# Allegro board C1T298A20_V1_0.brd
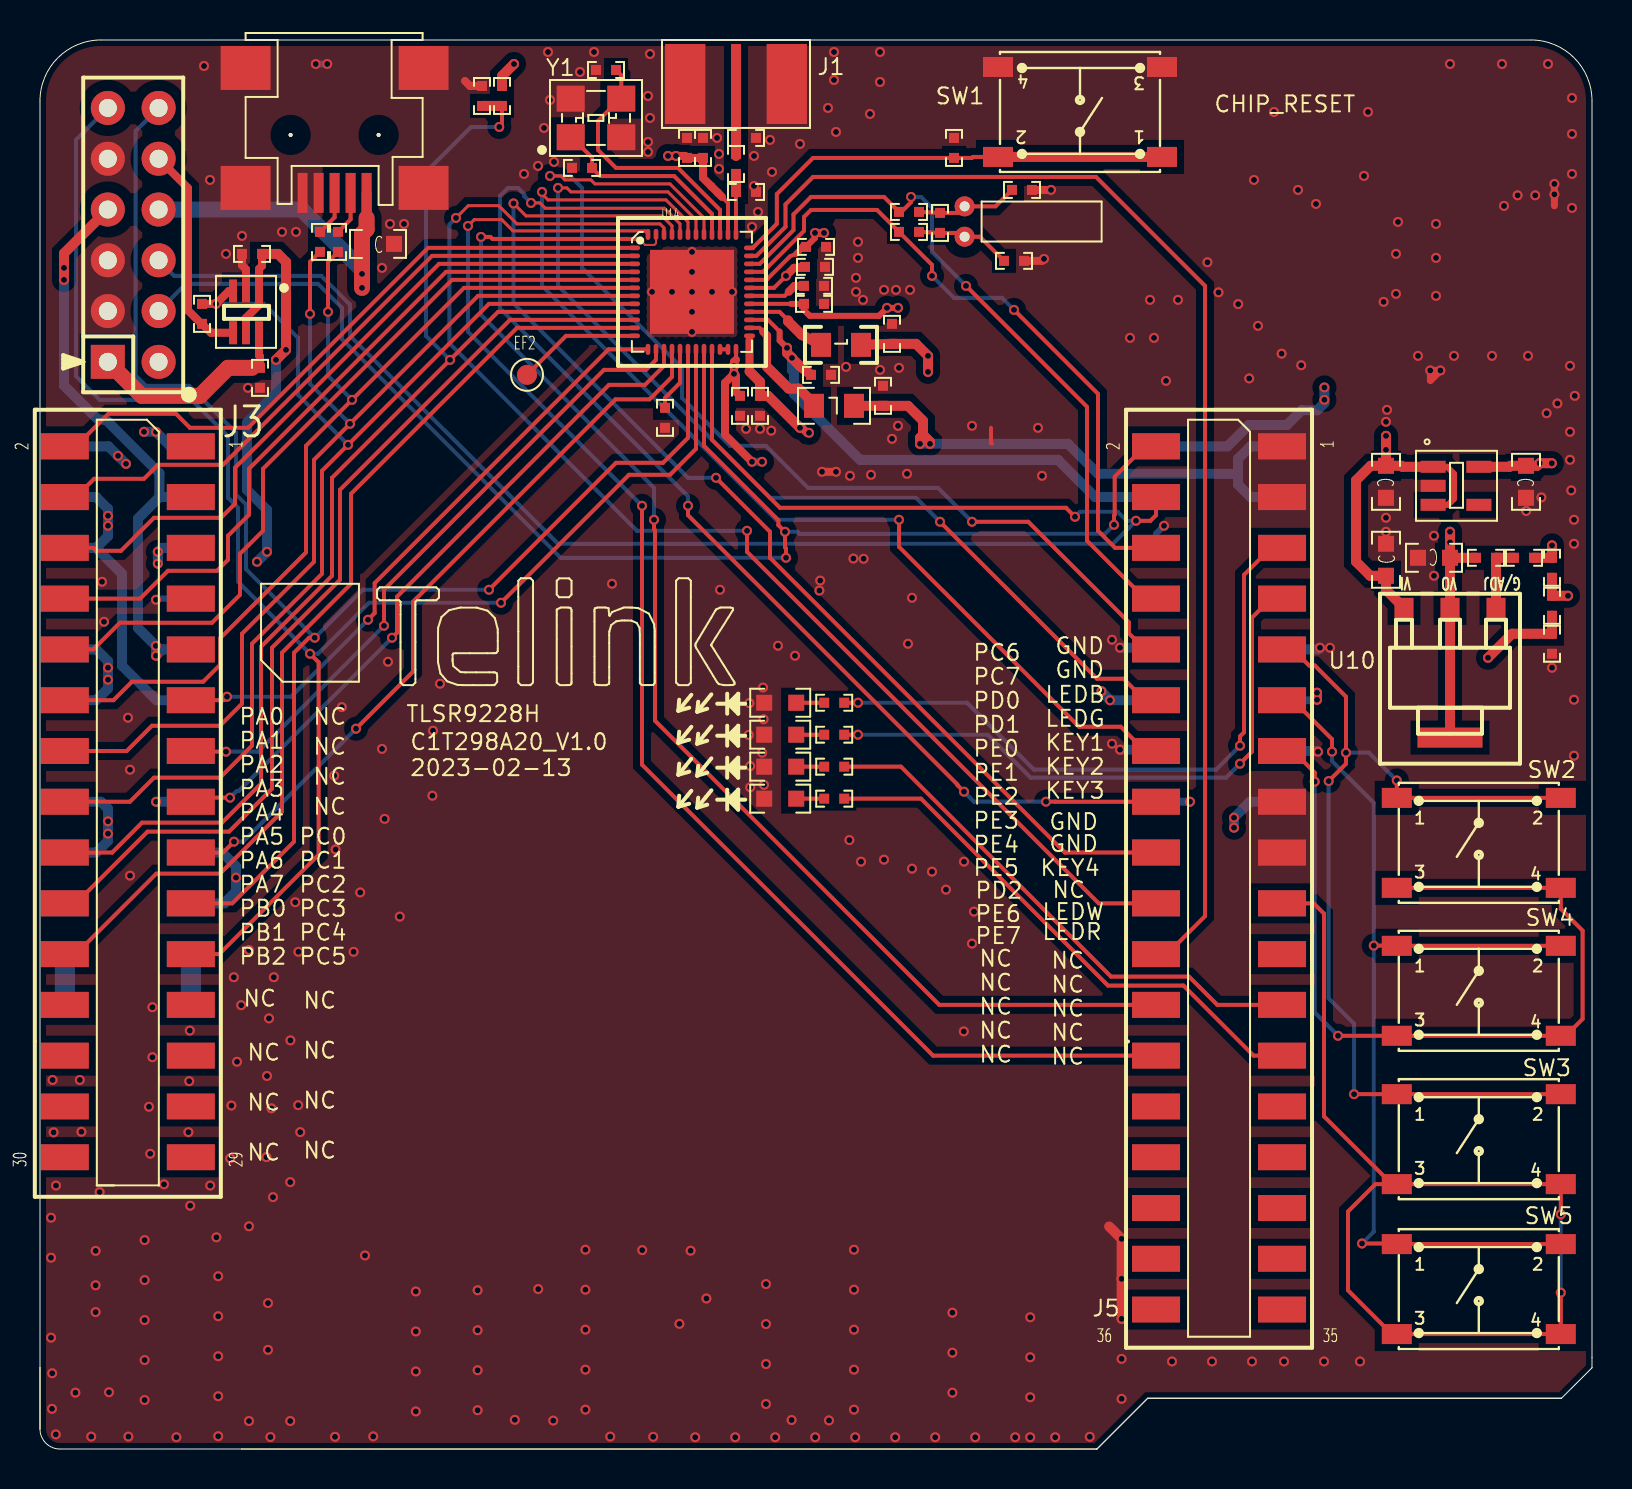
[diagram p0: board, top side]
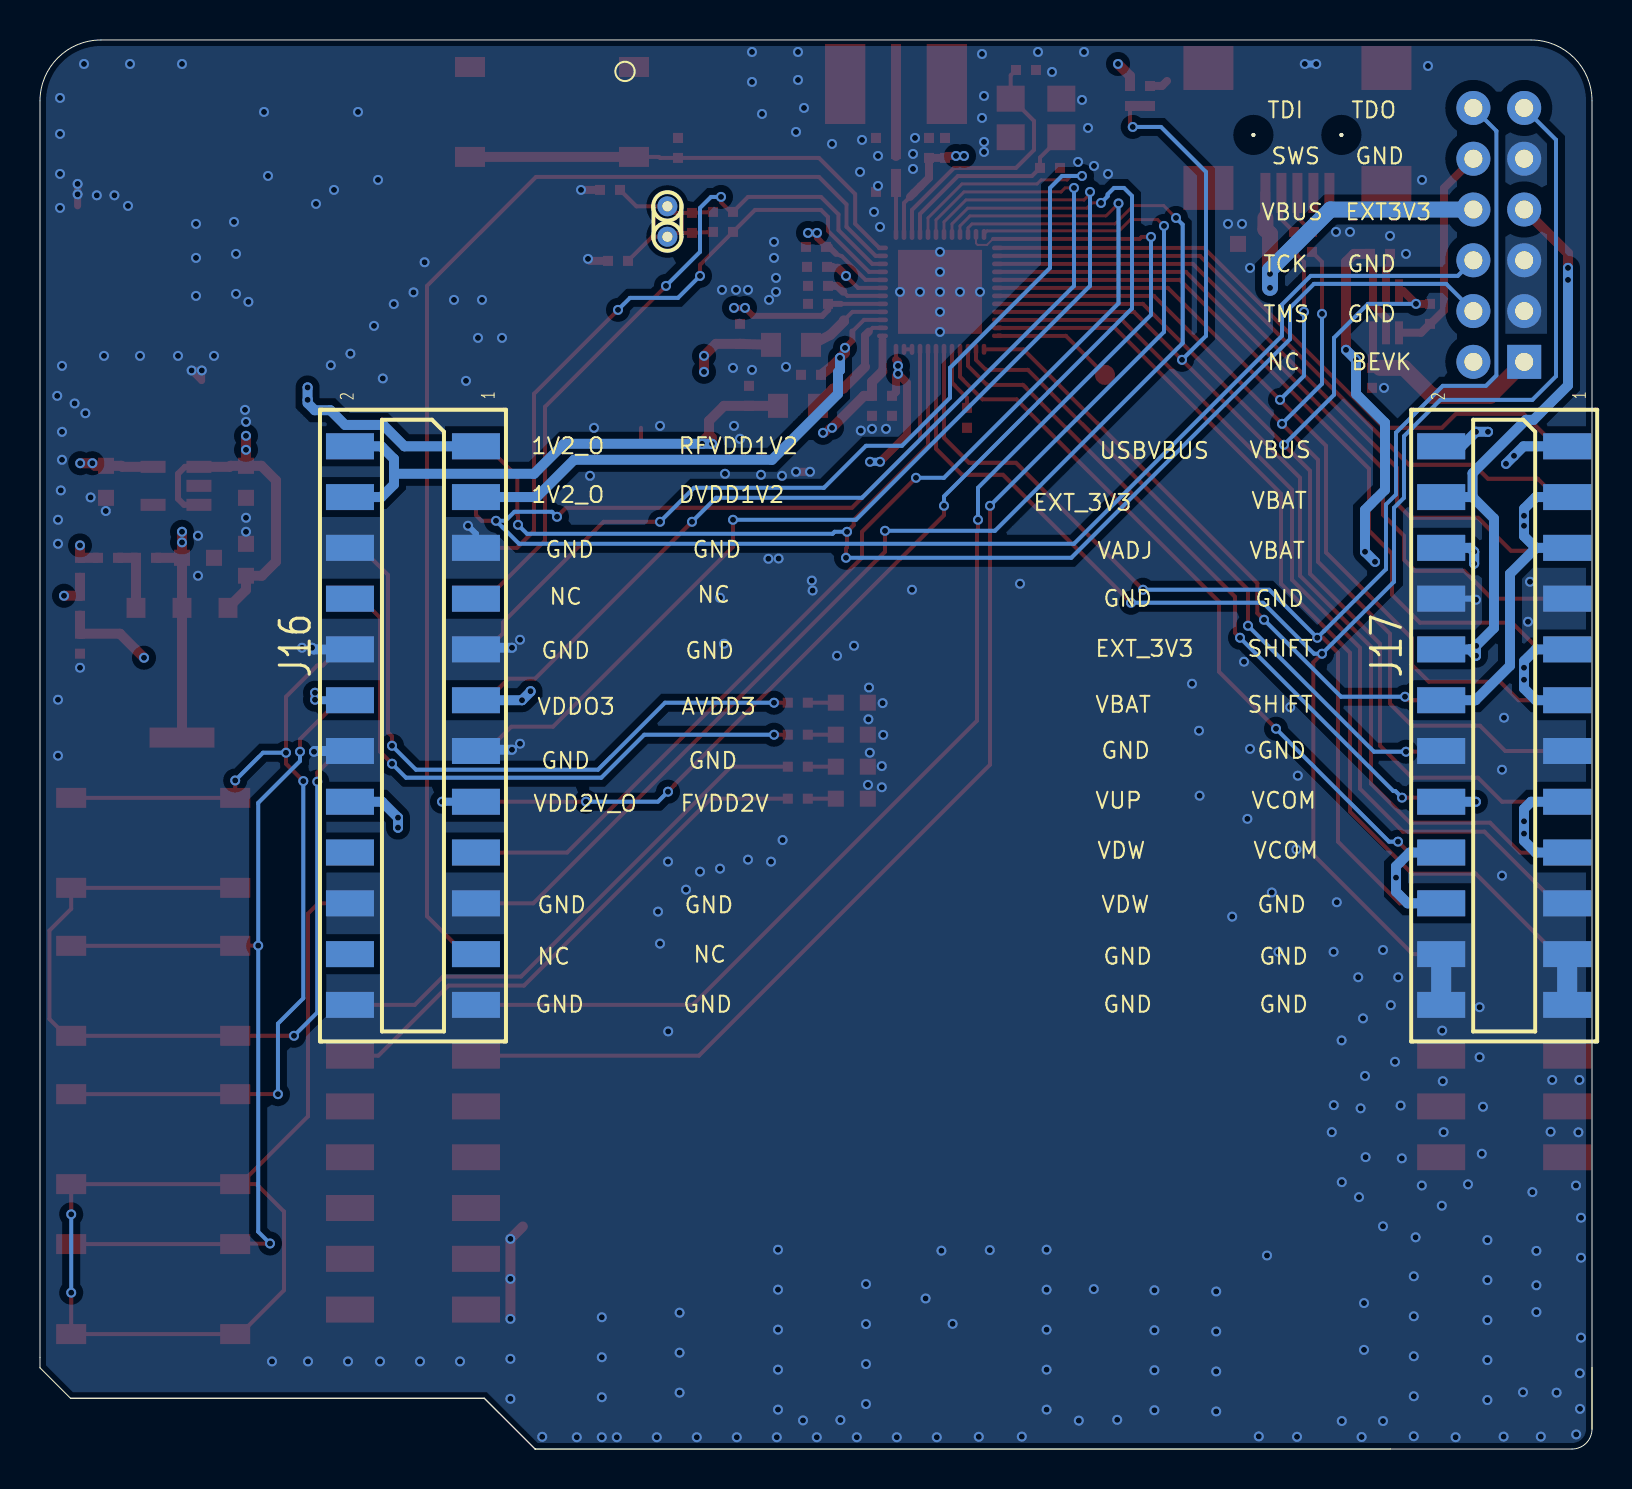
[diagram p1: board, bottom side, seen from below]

Outline 77.6 x 70.48 mm; copper layers: TOP, GND, POWER, BOTTOM. Coordinates in mm from the lower left corner of the outline.
Outline path: 0,4.08 0,67.43 arc(0.89,69.59) 3.05,70.48 74.55,70.48 arc(76.71,69.59) 77.6,67.43 77.6,4.06 76.08,2.54 76.07,2.54 ; 0,4.08 0,1 ; 0,4.08 0,1 ; 0,1 arc(0.29,0.29) 1,0 10.08,0 ; 10.08,0 52.84,0 ; 10.08,0 52.84,0 ; 52.84,0 52.85,0 ; 52.84,0 52.85,0 ; 52.85,0 55.39,2.54 ; 52.85,0 55.39,2.54 ; 55.39,2.54 76.07,2.54 ; 55.39,2.54 76.07,2.54

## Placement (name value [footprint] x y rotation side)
C1  NC  [0402]  28.3 68.98 0 top
C2  NC  [0402]  27.1 64.08 0 top
C3  0.1uF  [0402]  33.15 65.08 90 top
C4  2.2uF  [0402]  32.35 65.08 90 top
C5  NC  [0402]  35.3 62.88 180 top
C6  NC  [0402]  35.3 65.58 180 top
C7  NC  [0402]  48.7 59.43 180 top
C8  NC  [0402]  49.1 62.98 180 top
C9  1uF  [0402]  45.7 65.08 90 top
C10  1uF  [0402]  38.8 60.13 0 top
C11  1uF  [0402]  38.75 59.13 0 top
C12  1uF  [0402]  38.7 57.28 0 top
C13  1uF  [0402]  38.7 58.18 0 top
C14  1uF  [0402]  42.6 55.78 90 top
C17  1uF  [0402]  39.05 53.73 0 top
C18  1uF  [0402]  36 52.18 270 top
C21  1uF  [0402]  42.15 52.68 90 top
C23  1uF  [0402]  31.25 51.58 270 top
C30  10uF  [0603C]  16.9 60.28 0 top
C33  0.1uF  [0402]  10.6 59.78 180 top
C34  0.1uF  [0402]  11 53.58 270 top
C37  10uF  [0603C]  67.3 44.48 90 top
C38  10uF  [0603C]  67.3 48.38 270 top
C39  10uF  [0603C]  74.3 48.38 270 top
C40  10uF  [0603C]  69.7 44.58 180 top
C41  1uF  [0402]  35 52.18 270 top
D1  Blue  [0603-LED]  37.01 37.33 180 top
D2  Green  [0603-LED]  37.01 35.73 180 top
D3  White  [0603-LED]  37.01 34.13 180 top
D4  Red  [0603-LED]  37.01 32.53 180 top
EF2  TP  [TP100]  24.35 53.73 0 top
J1  RFIN  [SMA-H]  34.8 68.28 270 top
J3  HEADER 18X2  [SMD254M-2X15_RX1_30Y2_40]  4.39 23.49 90 top
J5  HEADER 18X2  [SMD254M-2X18_RX1_30Y2_40]  58.95 23.49 90 top
J11  USB_MiniABF  [USB-MINI-F5]  14.73 62.83 180 top
J15  JTAG  [HDR254F-2X6X850]  3.39 67.08 270 top
J16  HEADER 12X2  [SMD254M-2X12_RX1_30Y2_40]  58.95 36.19 90 bottom
J17  HEADER 12X2  [SMD254M-2X12_RX1_30Y2_40]  4.39 36.19 90 bottom
L1  0R  [0402]  34.8 64.28 90 top
L2  2.2uH  [0805L]  40.05 55.23 0 top
L3  2.2uH  [0805L]  39.7 52.18 0 top
R1  NC  [0402]  43.45 60.88 180 top
R2  NC  [0402]  43.45 61.88 180 top
R3  NC  [0402]  45 61.33 90 top
R4  1K  [0402]  39.71 37.33 180 top
R5  1K  [0402]  39.71 35.73 180 top
R6  1K  [0402]  39.71 34.13 180 top
R7  1K  [0402]  39.71 32.53 180 top
R14  33  [0402R]  14.9 60.38 270 top
R15  33  [0402R]  14 60.38 270 top
R16  NC/1K  [0402]  23.1 67.68 270 top
R17  1M/NC  [0402]  22.1 67.68 270 top
R26  0R  [0402R]  8.1 56.78 270 top
R33  430R  [0402]  74.2 44.58 0 top
R34  1.15K  [0402]  75.6 44.08 270 top
R35  787R  [0402]  75.6 42.18 270 top
R36  464R  [0402]  75.6 40.28 270 top
R37  1K  [0402]  72.3 44.58 180 top
SW1  SW4PIN_4.5x4.5  [SW_6X6_SMD]  52 66.88 180 top
SW2  SW4PIN_4.5x4.5  [SW_6X6_SMD]  71.94 30.32 0 top
SW3  SW4PIN_4.5x4.5  [SW_6X6_SMD]  71.94 15.5 0 top
SW4  SW4PIN_4.5x4.5  [SW_6X6_SMD]  71.94 22.92 0 top
SW5  SW4PIN_4.5x4.5  [SW_6X6_SMD]  71.94 8 0 top
U8  NC/TXS0101  [SC70-6]  10.3 56.88 180 top
U10  LM1117-ADJ  [SOT-223]  70.5 38.58 180 top
U11  CE1132-33M  [SOT-23-5]  70.8 48.18 270 top
U14  TLSR9228H  [QFN_6X6_48PIN_0P4_4P2X4P2]  32.6 57.88 0 top
Y1  24MHz-12pF-+/-20ppm  [OSCCC250X320X110]  27.8 66.58 90 top
Y2  32.768KHz - 9pf - +/-20ppm  [OSC_2X6]  50.23 61.4 180 top

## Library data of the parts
C1 C2 = C1005_NC
C3 C4 C9-C14 C17 C18 C21 C23 C38 C39 C41 = C1005X5R1C104K
C5-C8 = C1608_NC
C30 C37 = C1608X5R0J106M
C33 C34 C40 = C1608X5R1C105M
D1-D4 = 0603D_Green
EF2 = TestPad100
J1 = SMA_JACK_2
J3 = HEADER 18X2_0: Tolerance: RichardLC
J5 = HEADER 18X2: Tolerance: RichardLC
J11 = USB_MiniABF_5pin: User Part Number: pn; Tolerance: RichardLC
J15 = HEADER 6X2: User Part Number: pn; Tolerance: RichardLC
J16 J17 = HEADER 12X2: Tolerance: RichardLC
L1 = MLK1608_000R
L2 L3 = IND
R1-R3 R26 = RS0603K102JT
R4-R7 = RS0402K102JT
R14 R15 = RS0603K330JT
R16 R17 = RS0402K104JT
R33-R37 = RS0603K104JT
SW1-SW5 = SW_6X6_SMD_0
U8 = TXS0101
U10 = XC62FP3302_0.3V_SOT-89
U11 = XC6219_6.3V_SOT-23-5
U14 = TLSR9228H_0
Y1 = CRYSTAL4/SM_0: Tolerance: RichardLC
Y2 = OSC_2x6_2pin_16Mhz

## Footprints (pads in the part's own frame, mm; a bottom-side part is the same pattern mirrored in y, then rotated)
0402
  rect 0.5x0.5 smd: 1(-0.5,0) 2(0.5,0)
0402R
  rect 0.5x0.5 smd: 1(-0.5,0) 2(0.5,0)
0603-LED
  rect 0.8x0.8 smd: A(-0.8,0) C(0.8,0)
0603C
  rect 0.8x0.8 smd: 1(-0.8,0) 2(0.8,0)
0805L
  rect 1x1.2 smd: 1(-1,0) 2(1,0)
HDR254F-2X6X850
  rect 1.7x1.7 hole 0.9: 1(12.7,0)
  round 1.7 hole 0.9: 2(12.7,2.54) 3(10.16,0) 4(10.16,2.54) 5(7.62,0) 6(7.62,2.54) 7(5.08,0) 8(5.08,2.54) 9(2.54,0) 10(2.54,2.54) 11(0,0) 12(0,2.54)
OSC_2X6
  round 1 hole 0.5: 1(4,0.76) 2(4,-0.76)
OSCCC250X320X110
  rect 1.3x1.4 smd: 1(-0.965,1.265) 2(-0.965,-1.265) 3(0.965,-1.265) 4(0.965,1.265)
QFN_6X6_48PIN_0P4_4P2X4P2
  oval 0.55x0.23 smd: 1(-2.875,2.2) 2(-2.875,1.8) 3(-2.875,1.4) 4(-2.875,1) 5(-2.875,0.6) 6(-2.875,0.2) 7(-2.875,-0.2) 8(-2.875,-0.6) 9(-2.875,-1) 10(-2.875,-1.4) 11(-2.875,-1.8) 12(-2.875,-2.2) 25(2.875,-2.2) 26(2.875,-1.8) 27(2.875,-1.4) 28(2.875,-1) 29(2.875,-0.6) 30(2.875,-0.2) 31(2.875,0.2) 32(2.875,0.6) 33(2.875,1) 34(2.875,1.4) 35(2.875,1.8) 36(2.875,2.2)
  oval 0.23x0.55 smd: 13(-2.2,-2.875) 14(-1.8,-2.875) 15(-1.4,-2.875) 16(-1,-2.875) 17(-0.6,-2.875) 18(-0.2,-2.875) 19(0.2,-2.875) 20(0.6,-2.875) 21(1,-2.875) 22(1.4,-2.875) 23(1.8,-2.875) 24(2.2,-2.875) 37(2.2,2.875) 38(1.8,2.875) 39(1.4,2.875) 40(1,2.875) 41(0.6,2.875) 42(0.2,2.875) 43(-0.2,2.875) 44(-0.6,2.875) 45(-1,2.875) 46(-1.4,2.875) 47(-1.8,2.875) 48(-2.2,2.875)
  rect 4.2x4.2 smd: 49(0,0)
SC70-6
  rect 0.4x1.15 smd: 1(-0.65,-1.045) 2(0,-1.045) 3(0.65,-1.045) 4(0.65,1.045) 5(0,1.045) 6(-0.65,1.045)
SMA-H
  rect 4x0.5 smd: 1(0,0)
  rect 4x2 smd: 2(0,-2.54) 3(0,2.54) 4(0,-2.54) 5(0,2.54)
SMD254M-2X12_RX1_30Y2_40
  rect 1.3x2.4 smd: 1(13.97,-3.15) 2(13.97,3.15) 3(11.43,-3.15) 4(11.43,3.15) 5(8.89,-3.15) 6(8.89,3.15) 7(6.35,-3.15) 8(6.35,3.15) 9(3.81,-3.15) 10(3.81,3.15) 11(1.27,-3.15) 12(1.27,3.15) 13(-1.27,-3.15) 14(-1.27,3.15) 15(-3.81,-3.15) 16(-3.81,3.15) 17(-6.35,-3.15) 18(-6.35,3.15) 19(-8.89,-3.15) 20(-8.89,3.15) 21(-11.43,-3.15) 22(-11.43,3.15) 23(-13.97,-3.15) 24(-13.97,3.15)
SMD254M-2X15_RX1_30Y2_40
  rect 1.3x2.4 smd: 1(26.67,-3.15) 2(26.67,3.15) 3(24.13,-3.15) 4(24.13,3.15) 5(21.59,-3.15) 6(21.59,3.15) 7(19.05,-3.15) 8(19.05,3.15) 9(16.51,-3.15) 10(16.51,3.15) 11(13.97,-3.15) 12(13.97,3.15) 13(11.43,-3.15) 14(11.43,3.15) 15(8.89,-3.15) 16(8.89,3.15) 17(6.35,-3.15) 18(6.35,3.15) 19(3.81,-3.15) 20(3.81,3.15) 21(1.27,-3.15) 22(1.27,3.15) 23(-1.27,-3.15) 24(-1.27,3.15) 25(-3.81,-3.15) 26(-3.81,3.15) 27(-6.35,-3.15) 28(-6.35,3.15) 29(-8.89,-3.15) 30(-8.89,3.15)
SMD254M-2X18_RX1_30Y2_40
  rect 1.3x2.4 smd: 1(26.67,-3.15) 2(26.67,3.15) 3(24.13,-3.15) 4(24.13,3.15) 5(21.59,-3.15) 6(21.59,3.15) 7(19.05,-3.15) 8(19.05,3.15) 9(16.51,-3.15) 10(16.51,3.15) 11(13.97,-3.15) 12(13.97,3.15) 13(11.43,-3.15) 14(11.43,3.15) 15(8.89,-3.15) 16(8.89,3.15) 17(6.35,-3.15) 18(6.35,3.15) 19(3.81,-3.15) 20(3.81,3.15) 21(1.27,-3.15) 22(1.27,3.15) 23(-1.27,-3.15) 24(-1.27,3.15) 25(-3.81,-3.15) 26(-3.81,3.15) 27(-6.35,-3.15) 28(-6.35,3.15) 29(-8.89,-3.15) 30(-8.89,3.15) 31(-11.43,-3.15) 32(-11.43,3.15) 33(-13.97,-3.15) 34(-13.97,3.15) 35(-16.51,-3.15) 36(-16.51,3.15)
SOT-23-5
  rect 0.6x1.25 smd: 1(-0.95,-1.145) 2(0,-1.145) 3(0.95,-1.145) 4(0.95,1.145) 5(-0.95,1.145)
SOT-223
  rect 0.95x1 smd: 1(-2.3,-3.495) 2(0,-3.495) 3(2.3,-3.495)
  rect 3.25x1 smd: 4(0,2.995)
SW_6X6_SMD
  rect 1.5x1 smd: 1(-4.1,2.25) 2(4.1,2.25) 3(-4.1,-2.25) 4(4.1,-2.25)
TP100
  round 1 smd: 1(0,0)
USB-MINI-F5
  round 0.2 hole 0.9 unplated: (-2.2,-2.9) (2.2,-2.9)
  rect 0.5x2 smd: 1(-1.6,0) 2(-0.8,0) 3(0,0) 4(0.8,0) 5(1.6,0)
  rect 2.5x2.2 smd: 6(-4.45,-6.25) 7(4.45,-6.25) 8(-4.45,-0.25) 9(4.45,-0.25)

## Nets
GND: C1.1 C2.1 C3.2 C4.2 C5.1 C6.1 C7.1 C8.1 C9.2 C10.2 C11.2 C12.2 C13.2 C14.2 C17.2 C18.2 C21.2 C23.2 C30.2 C33.2 C34.2 C37.2 C38.2 C39.2 C40.2 C41.2 D1.C(CATHODE) D2.C(CATHODE) D3.C(CATHODE) D4.C(CATHODE) J1.2 J1.3 J1.4 J1.5 J5.1 J5.3 J5.15 J5.17 J11.4(ID) J11.5(GND) J11.6(S1) J11.7(S2) J11.8(S3) J11.9(S4) J15.3 J15.5 J15.9 J16.5 J16.6 J16.9 J16.10 J16.13 J16.14 J16.19 J16.20 J16.23 J16.24 J17.7 J17.8 J17.13 J17.14 J17.19 J17.21 J17.22 J17.23 J17.24 R17.1 R36.2 SW1.3 SW1.4 U8.2(GND) U11.2(VSS) U14.49(GND) Y1.2 Y1.4
VBAT_ADJ: C40.1 J17.6 R37.2 U10.2(VOUT#2) U10.4(VOUT#4)
VBUS: C30.1 C37.1 C38.1 J11.1(V_BUS) J15.8 J17.2 U10.3(VIN) U11.1(VIN) U11.3(CE)
BEVK_3V3: C34.1 J15.1 U8.6(VCCB)
BEVK_SWS: J15.10 R26.2 U8.4(B)
EXT_3V3: C39.1 J15.7 J17.4 J17.10 R16.1 U11.5(VOUT)
LED_B: J5.5 R4.1
LED_G: J5.7 R5.1
LED_R: J5.25 R7.1
LED_W: J5.23 R6.1
LEVEL_SHIFT: C33.1 J17.9 J17.11 U8.1(VCCA) U8.5(OE)
N: U14.22(N#22) U14.23(N#23)
TL_AVDD3: C10.1 J16.11 U14.32(AVDD3)
TL_DVDD1V2: C17.1 J16.3 U14.27(VDD1V4)
TL_FVDD2V: C12.1 J16.15 U14.29(FVDD2V)
TL_KEY1: J5.9 SW2.1 SW2.2 SW3.1 SW3.2
TL_KEY2: J5.11 SW4.1 SW4.2 SW5.1 SW5.2
TL_KEY3: J5.13 SW2.3 SW2.4 SW4.3 SW4.4
TL_KEY4: J5.19 SW3.3 SW3.4 SW5.3 SW5.4
TL_PA0: J3.2 U14.1(PA0)
TL_PA1: J3.4 U14.2(PA1)
TL_PA2: J3.6 U14.3(PA2)
TL_PA3: J3.8 U14.4(PA3)
TL_PA4: J3.10 U14.5(PA4)
TL_PA5_DM: J3.12 R14.2 U14.6(PA5)
TL_PA6_DP: J3.14 R15.2 U14.7(PA6)
TL_PA7_SWS: J3.16 R26.1 U8.3(A) U14.8(PA7)
TL_PB0: J3.18 R16.2 R17.2 U14.9(PB0)
TL_PB1: J3.20 U14.10(PB1)
TL_PB2: J3.22 U14.11(PB2)
TL_PC0: J3.11 U14.13(PC0)
TL_PC1: J3.13 U14.14(PC1)
TL_PC2: J3.15 U14.15(PC2)
TL_PC3: J3.17 U14.16(PC3)
TL_PC4_TDI: J3.19 J15.12 U14.18(PC4)
TL_PC5_TDO: J3.21 J15.11 U14.19(PC5)
TL_PC6_TMS: J5.2 J15.4 U14.20(PC6)
TL_PC7_TCK: J5.4 J15.6 U14.21(PC7)
TL_PD0_32K: J5.6 R1.2 U14.33(PD0)
TL_PD1_32K: J5.8 R2.2 U14.34(PD1)
TL_PD2: J5.22 U14.35(PD2)
TL_PE0: J5.10 U14.41(PE0)
TL_PE1: J5.12 U14.42(PE1)
TL_PE2: J5.14 U14.43(PE2)
TL_PE3: J5.16 U14.44(PE3)
TL_PE4: J5.18 U14.45(PE4)
TL_PE5: J5.20 U14.46(PE5)
TL_PE6: J5.24 U14.47(PE6)
TL_PE7: J5.26 U14.48(PE7)
TL_RFVDD1V2: C3.1 C4.1 J16.1 U14.38(VLINE_PAD)
TL_RST: C9.1 SW1.1 SW1.2 U14.36(RESETB)
TL_VBAT: C18.1 J17.3 J17.5 J17.12 U14.25(VBAT)
TL_VBUS: C11.1 J17.1 U14.31(VBUS)
TL_VDD1V2_O: C21.1 J16.2 J16.4 L3.2
TL_VDD2V_O: C14.1 J16.16 L2.2
TL_VDD3: C41.1 J16.12 U14.24(VDD3)
TL_XC1: C1.2 U14.39(XC1) Y1.3
TL_XC2: C2.2 U14.40(XC2) Y1.1
VCOM: J17.15 J17.17 R34.2 R35.1
VDW: J17.18 J17.20 R35.2 R36.1
VUP: J17.16 R33.2 R34.1
N20012529: C7.2 R1.1 R3.1 Y2.1
N20012531: C8.2 R2.1 R3.2 Y2.2
N20028206: R33.1 R37.1 U10.1(ADJ)
N20031284: C23.1 U14.17(VDDDEC)
N20031302: L3.1 U14.26(VDD1V4_O)
N20031350: L2.1 U14.28(VDD2V_O)
N20031395: C13.1 U14.30(VDDPST_F)
N20031510: C6.2 J1.1 L1.2
N20031514: C5.2 L1.1 U14.37(ANT)
N20050417: J11.3(D+) R15.1
N20050429: J11.2(D-) R14.1
N20105309: EF2.1(TP) U14.12(VDD25_EF)
N200358921: D4.A(ANODE) R7.2
N200359000: D1.A(ANODE) R4.2
N200359081: D2.A(ANODE) R5.2
N200359160: D3.A(ANODE) R6.2

Pads without a net: J3 1 3 5 7 9 23 24 25 26 27 28 29 30; J5 21 27 28 29 30 31 32 33 34 35 36; J15 2; J16 7 8 17 18 21 22; U11 4

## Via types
v1: diameter 0.5, hole 0.3, TOP to BOTTOM, 448 vias

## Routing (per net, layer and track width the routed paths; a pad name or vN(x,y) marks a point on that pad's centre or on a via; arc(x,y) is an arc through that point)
GND: length 30.7
  TOP w0.2: J5.3 61.55,47.62 ; 47.55,51.08 47.55,50.33 47.6,50.28
  TOP w0.35: v1(75.72,63.28) v1(75.72,62.76) 75.72,62.19 ; 69.52,53.45 69.52,53.94 v1(69.51,53.95) v1(70.02,53.95) 69.52,53.45
  TOP w0.4: v1(39.1,48.88) v1(39.8,48.88) ; v1(50.2,59.53) 50.1,59.43 C7.1 ; C33.2 10.1,59.21 10.3,59.01 U8.2 ; R17.1 21.5,68.18 21.25,68.43 ; C8.1 v1(50.55,62.98)
  TOP w0.5: 53.46,11.13 v1(54.08,10.51) v1(54.08,8.51) v1(54.08,6.51)
  BOTTOM w0.3: J17.8 5.86,42.54 v1(5.8,42.48) ; J16.5 55.8,45.78 v1(56.2,46.18)
  BOTTOM w0.35: v1(14.36,69.28) 14.3,69.28 13.8,69.28 13.8,69.28 v1(13.79,69.28)
  BOTTOM w0.5: v1(64,40.08) 63.92,40 J16.10 ; J16.14 63.86,34.92 v1(63.9,34.88) ; 56.2,40.08 v1(54,40.08) ; 55.4,34.98 v1(54,34.98)
  BOTTOM w1: J17.24 J17.22 ; J17.23 J17.21
  vias: v1(0.63,18.46) v1(0.55,11.57) v1(0.55,9.57) v1(0.55,5.57) v1(0.61,3.79) v1(0.6,2.01) v1(0.68,15.84) v1(0.8,13.18) v1(0.79,0.73) v1(1.77,2.82) v1(1.99,18.46) v1(2.07,15.87) v1(2.56,0.62) v1(2.78,9.91) v1(2.78,8.19) v1(2.78,6.85) v1(2.98,12.85) v1(3.1,43.38) v1(3.2,41.38) v1(3.45,2.84) v1(4.4,36.58) v1(4.42,0.62) v1(4.5,33.98) v1(4.5,28.68) v1(5.23,10.45) v1(5.23,8.45) v1(5.23,6.45) v1(5.23,4.45) v1(5.23,2.45) v1(5.45,17.12) v1(5.51,14.77) v1(5.62,22.1) v1(5.62,19.6) v1(6.2,13.24) v1(6.82,0.59) v1(7.42,15.85) v1(7.49,20.93) v1(7.46,18.4) v1(7.51,12.17) v1(8.2,69.18) v1(8.5,63.48) v1(8.51,13.18) v1(8.82,10.59) v1(8.91,8.64) v1(8.91,6.64) v1(8.91,4.64) v1(8.91,2.64) v1(8.91,0.64) v1(9.3,59.78) v1(9.51,14.54) v1(9.57,17.18) v1(9.69,23.6) v1(9.85,19.37) v1(10.1,60.68) v1(10.06,22.2) v1(10.4,53.08) v1(10.45,24.96) v1(10.45,11.14) v1(10.45,1.4) v1(11.35,18.66) v1(11.32,14.6) v1(11.45,21.54) v1(11.4,7.3) v1(11.4,4.96) v1(11.52,0.6) v1(11.57,17.04) v1(11.69,23.6) v1(11.65,12.6) v1(12.1,60.88) v1(12.52,20.44) v1(12.51,13.35) v1(12.51,1.4) v1(12.8,60.88) v1(12.76,27.35) v1(12.92,24.87) v1(12.91,17.2) v1(13.01,15.85) v1(14.71,33.68) v1(14.78,29.99) v1(14.75,0.61) v1(15.09,37.11) v1(15.68,24.87) v1(16.01,27.84) v1(16.25,9.68) v1(16.66,0.63) v1(17.1,59.08) v1(17.1,35.02) v1(17.23,31.52) v1(17.4,39.38) v1(17.5,61.28) v1(17.99,26.63) v1(18.2,61.28) v1(18.79,7.88) v1(18.79,5.88) v1(18.79,3.88) v1(18.79,1.88) v1(19.65,35.93) v1(19.62,32.68) v1(20,38.28) v1(21.88,7.94) v1(21.88,5.94) v1(21.88,3.94) v1(21.88,1.94) v1(23.74,1.46) v1(24.2,63.78) v1(24.9,64.18) v1(24.91,8) v1(25.2,66.08) v1(25.4,69.88) v1(25.5,67.48) v1(25.7,64.38) v1(25.66,1.42) v1(27,68.88) v1(27.27,9.97) v1(27.27,7.97) v1(27.27,5.97) v1(27.27,3.97) v1(27.27,1.97) v1(27.7,69.88) v1(28.51,0.62) v1(28.6,43.28) v1(30.11,9.95) v1(30.4,67.68) v1(30.4,65.38) v1(30.4,64.88) v1(30.5,69.78) v1(30.5,66.58) v1(30.6,57.88) v1(30.66,0.61) v1(31.6,57.88) v1(31.97,6.26) v1(32.53,9.92) v1(32.6,59.88) v1(32.6,58.88) v1(32.6,57.88) v1(32.6,56.88) v1(32.6,55.88) v1(32.76,0.59) v1(33.32,7.53) v1(33.6,57.88) v1(33.85,65.58) v1(33.95,64.78) v1(33.95,64.03) v1(34,42.98) v1(34.6,57.88) v1(34.76,0.59) v1(35.3,51.03) v1(35.44,35.72) v1(35.47,37.31) v1(35.51,34.16) v1(35.51,33.1) v1(35.6,61.13) v1(35.7,64.68) v1(35.7,63.18) v1(35.9,61.88) v1(36,51.03) v1(36.15,38.09) v1(36.11,34.83) v1(36.18,36.5) v1(36.2,33.22) v1(36.3,8.25) v1(36.3,6.25) v1(36.3,4.25) v1(36.3,2.25) v1(36.5,65.48) v1(36.6,63.88) v1(36.56,50.94) v1(36.76,0.59) v1(36.9,40.18) v1(37.58,1.45) v1(37.75,39.68) v1(38,65.28) v1(38.76,0.59) v1(39.01,43.44) v1(38.97,42.94) v1(39.4,67.08) v1(39.45,1.43) v1(39.7,69.88) v1(39.7,68.48) v1(39.8,65.88) v1(40.3,54.13) v1(40.5,48.68) v1(40.47,30.46) v1(40.67,44.54) v1(40.7,9.97) v1(40.7,7.97) v1(40.7,5.97) v1(40.7,3.97) v1(40.7,1.97) v1(40.8,58.58) v1(40.8,57.88) v1(40.76,0.59) v1(40.9,60.38) v1(40.9,59.58) v1(41.05,29.38) v1(41.15,57.48) v1(41.18,44.53) v1(41.5,66.78) v1(41.55,48.73) v1(42,69.88) v1(42,68.38) v1(42,53.98) v1(42.2,57.98) v1(42.2,29.48) v1(42.6,50.53) v1(42.8,57.98) v1(42.76,0.59) v1(42.9,51.18) v1(42.95,54.08) v1(43.35,48.78) v1(43.4,40.28) v1(43.5,57.98) v1(43.6,42.58) v1(43.6,29.03) v1(44.6,28.88) v1(44.76,0.59) v1(45.3,27.98) v1(45.62,6.82) v1(45.62,4.82) v1(45.62,2.82) v1(46.2,29.38) v1(46.19,20.89) v1(46.6,51.18) v1(46.6,25.28) v1(46.7,26.88) v1(46.76,0.59) v1(48.76,0.59) v1(49.51,6.59) v1(49.51,4.59) v1(49.51,2.59) v1(49.51,0.59) v1(49.9,51.08) v1(50.1,48.68) v1(50.76,0.59) v1(52.49,0.61) v1(53.6,40.48) v1(53.6,35.28) v1(54.08,4.51) v1(54.08,2.51) v1(54.5,55.58) v1(55.5,57.48) v1(55.7,55.58) v1(56.3,53.43) v1(56.6,4.38) v1(56.9,57.48) v1(58.37,59.36) v1(58.6,4.38) v1(58.92,57.86) v1(59.91,57.27) v1(60.46,53.55) v1(60.6,4.38) v1(60.7,63.48) v1(60.9,56.18) v1(61.7,66.88) v1(62.08,54.79) v1(62.2,4.38) v1(62.9,62.98) v1(63.06,54.21) v1(63.8,62.28) v1(64.2,4.38) v1(64.5,40.08) v1(66,4.38) v1(66.2,63.68) v1(66.4,66.88) v1(67.18,57.38) v1(67.35,51.98) v1(67.3,51.38) v1(67.3,46.58) v1(67.3,45.88) v1(67.8,59.78) v1(67.8,57.78) v1(67.9,61.38) v1(68.9,54.68) v1(69.7,45.68) v1(69.7,43.68) v1(69.8,61.28) v1(69.8,59.58) v1(69.8,57.68) v1(70.5,69.28) v1(70.7,54.68) v1(72.6,54.68) v1(73.1,69.28) v1(73.2,62.18) v1(73.88,62.71) v1(74.31,46.92) v1(74.4,54.68) v1(74.76,62.71) v1(75.07,47.6) v1(75.33,51.81) v1(75.4,69.28) v1(75.6,39.08) v1(75.87,52.3) v1(76.5,54.18) v1(76.5,50.88) v1(76.5,49.48) v1(76.6,67.58) v1(76.6,65.78) v1(76.6,63.78) v1(76.6,62.08) v1(76.56,47.95) v1(76.74,52.68) v1(76.7,46.48) v1(76.7,45.28) v1(76.7,37.48) v1(76.7,34.68)
VBAT_ADJ: length 13.9
  TOP w0.5: C40.1 v1(70.5,45.35) v1(70.5,45.88) ; C40.1 R37.2 ; C40.1 U10.2 70.5,35.59
  BOTTOM w0.5: J17.6 6.1,45.08 5.9,44.88 v1(5.89,44.88) v1(5.89,44.29)
VBUS: length 36.9
  TOP w0.3: U11.3 70.4,47.23 70.7,47.53 70.7,48.78 70.35,49.13 U11.1
  TOP w0.5: 16.33,61.57 J11.1 ; C38.1 68.07,49.18 68.12,49.13 U11.1 ; C38.1 66.53,49.18 65.8,48.45 65.8,44.39 66.51,43.68 C37.1 67.3,42.98 U10.3 ; C38.1 v1(67.3,49.98) v1(67.3,50.68)
  TOP w0.8: v1(16.1,58.08) v1(16.1,58.78) C30.1 16.1,60.78 16.33,61.01 16.33,61.57
  BOTTOM w0.5: v1(5.2,50.88) v1(5.8,50.88) 6.52,50.16 J17.2
  BOTTOM w0.8: J15.8 13.08,62 16.1,58.98 v1(16.1,58.78) v1(16.1,58.08)
BEVK_3V3: length 10.7
  TOP w0.4: U8.6 10.95,54.7 11,54.65 C34.1 10.6,54.08
  TOP w0.8: J15.1 5.09,52.68 8,52.68 9.4,54.08 10.6,54.08
BEVK_SWS: length 10.9
  TOP w0.4: J15.10 7.4,63.07 7.4,56.96 8.08,56.28 R26.2 8.54,55.84 U8.4
EXT_3V3: length 35.7
  TOP w0.5: R16.1 23.1,68.68 v1(23.7,69.28) ; v1(75.59,49.31) v1(74.98,49.31) 74.85,49.18 C39.1 73.53,49.18 73.48,49.13 U11.5 ; v1(1.2,58.48) v1(1.2,59.08) 1.2,59.81 J15.7
  BOTTOM w0.5: 6.12,40 5.97,40 5.8,40.17 ; 6.12,40 J17.10 ; 6.12,40 v1(5.8,39.68) 5.8,40.17 ; 5.8,40.17 v1(5.79,40.17) 4.9,41.07 4.9,46.54 5.97,47.62 ; v1(1.2,59.08) v1(1.2,58.48) 1.2,53.2 2.92,51.48 3.3,51.48 5.97,48.81 5.97,47.62 ; 5.97,47.62 J17.4
LED_B: length 32.8
  TOP w0.2: J5.5 61.55,45.08 60.2,43.72 60.2,35.85 60,35.65 v1(60,35.18) ; R4.1 v1(40.9,37.33)
  BOTTOM w0.2: v1(40.9,37.33) 46.35,37.33 49.7,33.98 58.8,33.98 v1(60,35.18)
LED_G: length 30.4
  TOP w0.2: R5.1 v1(40.9,35.73) ; J5.7 61.55,42.54 60.6,41.58 60.6,34.88 v1(60,34.28)
  BOTTOM w0.2: v1(60,34.28) 59.3,33.58 49.53,33.58 47.38,35.73 v1(40.9,35.73)
LED_R: length 27.2
  TOP w0.2: J5.25 60.68,19.68 57.18,23.18 53.4,23.18 44.05,32.53 R7.1
LED_W: length 26.8
  TOP w0.2: J5.23 58.86,22.22 57.45,23.63 53.55,23.63 43.05,34.13 R6.1
LEVEL_SHIFT: length 28.9
  TOP w0.4: U8.5 10.3,56.58 10.95,57.23 U8.1 10.95,59.03 11.1,59.18 C33.1
  TOP w0.5: v1(11.8,54.48) v1(12.3,54.98) 12.3,59.38 11.9,59.78 C33.1
  BOTTOM w0.5: v1(12.3,54.98) v1(11.8,54.48) 11.8,52.78 10.35,51.33 10.35,47.97 11.35,46.97 v1(11.35,44.88) v1(10.85,44.38) ; J17.11 2.81,37.46 3.4,38.04 v1(3.4,38.48) v1(3.4,39.08) 3.4,39.41 2.81,40 J17.9
N: length 0.4
  TOP w0.2: U14.23 U14.22
TL_AVDD3: length 7.7
  TOP w0.2: 37.8,59.78 37.5,59.65 36.32,58.48 U14.32
  TOP w0.3: v1(38.75,60.83) 38.75,60.58 C10.1 ; 37.8,59.78 38.15,60.13
  TOP w0.4: v1(38.75,60.83) v1(39.2,60.83) ; 38.15,60.13 C10.1
  BOTTOM w0.5: v1(53.07,37.91) 53.07,37.88 v1(53.5,37.46) J16.11
TL_DVDD1V2: length 26.7
  TOP w0.2: U14.27 36.4,56.48 36.98,55.9
  TOP w0.3: v1(37.35,55.08) 36.98,55.45 36.98,55.9
  TOP w0.5: v1(37.35,55.08) 37.35,54.83 v1(37.6,54.58) 37.58,54.58 37.98,54.18 C17.1
  BOTTOM w0.5: v1(37.6,54.58) 37.6,53.96 37.7,53.86 37.7,52.78 41,49.48 50.9,49.48 52.76,47.62 J16.3
TL_FVDD2V: length 9.7
  TOP w0.2: U14.29 37.55,57.28
  TOP w0.3: 38.19,57.28 38.19,56.98 38.49,56.68 41.95,56.68 v1(42.35,57.08) v1(42.9,57.08) ; 38.19,57.28 38.2,57.28 C12.1 ; 38.19,57.28 37.55,57.28
  BOTTOM w0.4: v1(57.5,32.38) 57.35,32.38 57.35,32.38 J16.15
TL_KEY1: length 47.5
  TOP w0.2: v1(64.43,33.41) 65.3,34.28 v1(65.3,34.83) 65.3,37.63 63.74,39.19 63.46,39.19 62.65,40 J5.9 ; v1(67.84,33.44) SW2.1 SW2.2 ; SW3.2 SW3.1 v1(65.7,17.75)
  BOTTOM w0.2: v1(65.7,17.75) 65.7,21.28 64.43,22.55 v1(64.43,33.41) ; v1(65.3,34.83) 66.45,34.83 v1(67.84,33.44)
TL_KEY2: length 48.9
  TOP w0.2: SW4.2 SW4.1 67.27,25.17 67.26,25.18 v1(66.69,25.18) ; J5.11 62.65,37.46 64.6,35.51 v1(64.6,34.88) ; SW5.2 SW5.1 67.27,10.25 67.24,10.28 v1(66.1,10.28)
  BOTTOM w0.2: v1(66.1,10.28) 66.69,10.87 v1(66.69,25.18) 66.69,32.32 64.6,34.41 v1(64.6,34.88)
TL_KEY3: length 43.5
  TOP w0.2: J5.13 62.65,34.92 63.74,33.83 v1(63.74,33.38) ; v1(64.9,20.67) SW4.3 SW4.4 76.29,20.67 77.13,21.51 77.13,25.93 76.04,27.02 SW2.4 SW2.3
  BOTTOM w0.2: v1(63.74,33.38) 63.74,21.83 v1(64.9,20.67)
TL_KEY4: length 51.4
  TOP w0.2: v1(76.04,7.82) SW5.4 SW5.3 67.59,5.75 65.4,7.94 65.4,11.88 66.77,13.25 67.59,13.25 ; 67.59,13.25 64.2,16.64 64.2,26.78 63.68,27.3 J5.19 ; 67.59,13.25 SW3.3 SW3.4 v1(76.04,11.74)
  BOTTOM w0.2: v1(76.04,11.74) v1(76.04,7.82)
TL_PA0: length 33.2
  TOP w0.2: J3.2 1.79,50.16 3.42,51.78 6.8,51.78 7.5,51.08 10.4,51.08 19.4,60.08 U14.1
TL_PA1: length 33.5
  TOP w0.2: U14.2 19.6,59.68 9.15,49.23 5.9,49.23 5.2,48.53 2.71,48.53 1.79,47.62 J3.4
TL_PA2: length 35.5
  TOP w0.2: U14.3 19.95,59.28 9.75,49.08 9.75,47.28 9.05,46.58 5.7,46.58 4.05,44.93 2.81,44.93 2.66,45.08 J3.6
TL_PA3: length 37.3
  TOP w0.2: J3.8 5.01,42.54 6.4,43.93 8.85,43.93 9.4,44.48 9.4,45.68 10.45,46.73 10.45,49.03 20.3,58.88 U14.4
TL_PA4: length 39.2
  TOP w0.2: U14.5 20.6,58.48 11.15,49.03 11.15,45.93 10,44.78 10,42.73 8.6,41.33 4,41.33 2.66,40 J3.10
TL_PA5_DM: length 49
  TOP w0.2: J3.12 3.68,37.46 4.6,38.38 8.16,38.38 9.01,39.23 9.01,40.56 13.3,44.85 13.3,50.18 v1(15.6,52.48) 21.2,58.08 U14.6 ; R14.2 14.4,59.38 v1(14.4,56.88)
  BOTTOM w0.2: v1(15.6,52.48) 14.4,53.68 v1(14.4,56.88)
TL_PA6_DP: length 52.6
  TOP w0.2: R15.2 13.5,59.38 v1(13.5,56.78) ; U14.7 21.9,57.68 v1(15.5,51.28) 13.7,49.48 13.7,44.38 10.1,40.78 10.1,37.28 9,36.18 5.6,36.18 4.34,34.92 J3.14
  BOTTOM w0.2: v1(15.5,51.28) 13.5,53.28 v1(13.5,56.78)
TL_PA7_SWS: length 57.8
  TOP w0.2: U14.8 22.45,57.28 v1(15.4,50.23) 14.1,48.93 14.1,43.78 10.6,40.28 10.6,35.18 9,33.58 5.7,33.58 4.5,32.38 J3.16
  TOP w0.4: R26.1 v1(8.8,57.28) 9.45,57.93 U8.3
  BOTTOM w0.2: v1(8.8,57.28) 11.2,57.28 12.9,55.58 12.9,52.73 v1(15.4,50.23)
TL_PB0: length 63.2
  TOP w0.2: R16.2 23.1,66.27 v1(22.96,66.13) ; J3.18 3.61,29.84 5.1,31.33 9.1,31.33 11.05,33.28 11.05,40.13 14.6,43.68 14.6,48.58 v1(20.5,54.48) 22.9,56.88 U14.9
  TOP w0.5: R17.2 R16.2
  BOTTOM w0.2: v1(20.5,54.48) 19.3,55.68 19.3,63.88 21.55,66.13 v1(22.96,66.13)
TL_PB1: length 47.3
  TOP w0.2: J3.20 1.79,27.3 5.38,30.88 9.45,30.88 11.6,33.03 11.6,40.08 15,43.48 15,47.98 23.5,56.48 U14.10
TL_PB2: length 48.8
  TOP w0.2: J3.22 1.79,24.76 5.82,28.78 9,28.78 12.1,31.88 12.1,39.83 15.55,43.28 15.55,47.78 23.85,56.08 U14.11
TL_PC0: length 31
  TOP w0.2: v1(9.35,37.63) 9.18,37.46 J3.11 ; U14.13 28.43,55.01 16.73,43.31 16.73,41.81 v1(16.4,41.48)
  BOTTOM w0.2: v1(9.35,37.63) 12.55,37.63 v1(16.4,41.48)
TL_PC1: length 33
  TOP w0.2: v1(17.2,41.18) 17.2,42.98 28.2,53.98 30.3,53.98 30.8,54.48 U14.14 ; v1(9.3,34.88) 7.58,34.88 J3.13
  BOTTOM w0.2: v1(9.3,34.88) 10.9,34.88 v1(17.2,41.18)
TL_PC2: length 34.6
  TOP w0.2: v1(9.5,32.58) 7.75,32.58 J3.15 ; v1(17.6,40.58) 17.85,40.83 17.85,42.63 28.45,53.23 30.25,53.23 31.2,54.18 U14.15
  BOTTOM w0.2: v1(9.5,32.58) 9.83,32.91 9.93,32.91 v1(17.6,40.58)
TL_PC3: length 37.3
  TOP w0.2: U14.16 31.6,53.63 30.48,52.51 28.77,52.51 18.65,42.38 18.65,38.88 v1(15.8,36.03) ; v1(9.7,30.38) 9.16,29.84 J3.17
  BOTTOM w0.2: v1(9.7,30.38) 10.15,30.38 v1(15.8,36.03)
TL_PC4_TDI: length 76.4
  TOP w0.2: U14.18 32.4,50.58 31.15,49.33 28.8,49.33 v1(22.45,42.98) ; J3.19 9.62,27.3 12.7,30.38 12.7,39.83 13.45,40.58 v1(13.74,40.58)
  BOTTOM w0.2: v1(22.45,42.98) 16.14,42.98 v1(13.74,40.58) 13.4,40.91 13.4,40.91 10.3,44.01 10.3,47.25 9.8,47.75 9.8,50.84 7.46,53.18 5.3,53.18 4.78,53.7 4.78,65.93 J15.12
TL_PC5_TDO: length 82.7
  TOP w0.2: v1(13.5,39.78) 13.93,39.35 13.93,29.73 8.96,24.76 J3.21 ; v1(23.05,42.33) 29.45,48.73 31.5,48.73 32.8,50.03 U14.19
  BOTTOM w0.2: v1(23.05,42.33) 16.45,42.33 13.9,39.78 v1(13.5,39.78) 9.9,43.38 9.9,47.08 9.4,47.58 9.4,50.66 7.58,52.48 2.98,52.48 1.8,53.66 1.8,65.49 J15.11
TL_PC6_TMS: length 72.4
  TOP w0.2: v1(37.3,44.58) 37.3,45.05 37.25,45.1 v1(37.25,45.88) 36.92,46.21 36.92,46.46 33.2,50.18 U14.20 ; J5.2 55.25,50.16 53.74,48.64 53.74,46.74 53.7,46.7 v1(53.7,46.23)
  BOTTOM w0.2: v1(37.25,45.88) 37.87,45.88 37.97,45.78 53.25,45.78 v1(53.7,46.23) ; v1(37.3,44.58) 26.03,44.58 15.1,55.51 15.1,57.08 13.9,58.28 7.29,58.28 J15.4
TL_PC7_TCK: length 85.8
  TOP w0.2: v1(51.75,46.63) 51.3,47.08 37,47.08 33.6,50.48 U14.21 ; v1(54.8,46.43) 55.52,46.43 55.8,46.71 J5.4
  BOTTOM w0.2: v1(51.75,46.63) 52,46.88 53.88,46.88 54.33,46.43 v1(54.8,46.43) 54.47,46.1 54.47,46.1 53.65,45.28 25.9,45.28 15.5,55.68 15.5,57.25 14.07,58.68 6.71,58.68 J15.6
TL_PD0_32K: length 33.4
  TOP w0.2: v1(44.6,58.68) 44.6,59.23 R1.2 41.85,61.98 38.55,61.98 38.2,61.63 38.2,60.93 36.15,58.88 U14.33 ; J5.6 53.75,45.08 52.9,45.93 52.9,52.78 v1(48.7,56.98)
  BOTTOM w0.2: v1(44.6,58.68) 45.7,57.58 48.1,57.58 v1(48.7,56.98)
TL_PD1_32K: length 36.5
  TOP w0.2: U14.34 35.98,59.28 37.68,60.97 37.68,61.76 38.55,62.63 42.2,62.63 R2.2 43.07,61.88 43.55,62.36 v1(43.55,62.63) ; J5.8 55.25,42.54 52.35,45.44 52.35,52.13 v1(46.3,58.18)
  BOTTOM w0.2: v1(46.3,58.18) 44.6,59.88 44.6,62.08 44.05,62.63 v1(43.55,62.63)
TL_PD2: length 62.1
  TOP w0.2: J5.22 56.35,24.76 58.25,26.65 58.25,58.18 52.8,63.63 38.65,63.63 37.28,62.26 37.28,61.14 35.82,59.68 U14.35
TL_PE0: length 53.1
  TOP w0.15: U14.41 33.2,61.58 31.5,63.28 27.75,63.28 27.55,63.48 26.25,63.48 26.05,63.68 v1(25.5,63.68)
  TOP w0.2: v1(46.6,46.38) 49.42,46.38 54.45,41.35 54.45,40.8 55.25,40 J5.10
  BOTTOM w0.2: v1(25.5,63.68) 26.5,63.68 27.1,63.08 27.1,59.08 32.1,54.08 32.1,52.58 34.5,50.18 36.3,50.18 38.4,48.08 44.9,48.08 v1(46.6,46.38)
TL_PE1: length 51.7
  TOP w0.15: U14.42 32.8,61.48 31.4,62.88 26.55,62.88 26.34,63.08 v1(25.9,63.08)
  TOP w0.2: J5.12 55.25,37.46 54.18,38.53 52.85,38.53 v1(45,46.38)
  BOTTOM w0.2: v1(25.9,63.08) 25.9,58.18 36.5,47.58 43.8,47.58 v1(45,46.38)
TL_PE2: length 54.4
  TOP w0.15: U14.43 32.4,61.38 31.3,62.48 25.4,62.48 25.1,62.78 v1(25.1,62.88)
  TOP w0.2: J5.14 55.25,34.92 54.04,36.13 51.95,36.13 42.95,45.13 v1(42.95,46.48)
  BOTTOM w0.2: v1(25.1,62.88) 25.1,58.18 36.8,46.48 v1(42.95,46.48)
TL_PE3: length 59.7
  TOP w0.15: v1(24.55,62.33) 25,62.33 25.26,62.07 31.21,62.07 32,61.28 U14.44
  TOP w0.2: J5.16 50.77,32.38 50.77,32.38 v1(50.3,32.38) ; v1(46.2,32.88) 45.87,33.21 45.87,33.24 32.4,46.71 v1(32.4,47.18)
  BOTTOM w0.2: v1(32.4,47.18) 32.4,47.65 23,57.05 23,62.68 23.4,63.08 23.9,63.08 24.22,62.76 24.22,62.66 v1(24.55,62.33) ; v1(50.3,32.38) 46.7,32.38 v1(46.2,32.88)
TL_PE4: length 58.1
  TOP w0.15: U14.45 31.6,61.18 31.1,61.68 24.3,61.68 v1(23.68,62.31)
  TOP w0.2: v1(33.8,48.58) 36.5,45.88 36.5,44.58 51.24,29.84 J5.18
  BOTTOM w0.2: v1(23.68,62.31) 23.68,57.31 32.4,48.58 v1(33.8,48.58)
TL_PE5: length 65.4
  TOP w0.15: U14.46 31.2,61.08 31,61.28 23.85,61.28 22.94,62.19 21.41,62.19 v1(20.8,61.58)
  TOP w0.2: J5.20 52.93,27.3 35.35,44.88 v1(35.35,45.93)
  BOTTOM w0.2: v1(20.8,61.58) 20.47,61.25 20.47,55.31 29.85,45.93 v1(35.35,45.93)
TL_PE6: length 68.1
  TOP w0.1: 29.95,60.53 30.25,60.23 30.72,60.23 30.8,60.31 U14.47
  TOP w0.2: 29.95,60.53 22.62,60.53 22.52,60.63 v1(22.05,60.63) ; v1(30.7,46.48) 30.7,46.01 30.75,45.96 30.75,36.43 44.96,22.22 J5.24
  BOTTOM w0.2: v1(22.05,60.63) 22.05,56.73 30.7,48.08 v1(30.7,46.48)
TL_PE7: length 71.7
  TOP w0.15: U14.48 30.4,60.78 30.25,60.93 23.65,60.93 23.09,61.49 21.71,61.49 v1(21.4,61.18)
  TOP w0.2: v1(30.1,47.18) 30.1,34.23 44.65,19.68 J5.26
  BOTTOM w0.2: v1(21.4,61.18) 21.4,55.88 v1(30.1,47.18)
TL_RFVDD1V2: length 16.2
  TOP w0.2: 34.1,62.63 34.4,62.33 U14.38
  TOP w0.4: 34.1,62.63 33.9,62.83 33.15,63.58 C3.1 C4.1 32.25,64.68 v1(31.8,64.68) v1(31.4,64.68)
  BOTTOM w0.5: J16.1 59.38,50.16 60.45,51.23 62.35,51.23 63.08,51.96 63.86,51.96 64.22,52.32 v1(64.22,52.48) v1(64.22,53.1)
TL_RST: length 23.4
  TOP w0.2: SW1.2 46.65,64.63 46.6,64.58 C9.1 38.65,64.58 36.84,62.77 36.84,61.29 35.63,60.08 U14.36
  TOP w0.5: SW1.1 SW1.2
TL_VBAT: length 24.3
  TOP w0.2: 35.48,55.46 U14.25
  TOP w0.4: 35.48,53.91 35.48,55.46 ; v1(38,51.08) 38.1,51.08 38.35,50.83 v1(38.45,50.83)
  TOP w0.5: v1(38,51.08) 36.4,52.68 C18.1 36,53.38 35.48,53.91
  POWER w0.2: 24.27,52.41 23.91,52.06 23.81,52.06 23.48,51.73
  BOTTOM w0.5: J17.12 5.82,37.46 4.1,39.18 4.1,43.78 2.81,45.07 2.81,45.08 ; J17.5 2.81,45.08 ; 2.81,45.08 3.4,45.66 v1(3.4,46.18) v1(3.4,46.68) 3.4,47.03 2.81,47.62 J17.3
TL_VBUS: length 6.6
  TOP w0.2: U14.31 36.7,58.08 v1(37.3,58.68)
  TOP w0.4: v1(37.3,58.68) 37.7,59.08 37.95,59.08 38,59.13 C11.1
  BOTTOM w0.5: J17.1 3.42,50.16 v1(3.9,49.68) v1(4.3,49.28)
TL_VDD1V2_O: length 28.3
  TOP w0.5: 44.15,50.73 44,50.58 v1(44,50.28) ; 44.15,50.73 44.15,51.43 43.4,52.18 C21.1 L3.2 ; 44.15,50.73 44.5,50.38 v1(44.5,50.28)
  BOTTOM w0.5: J16.4 60.53,47.62 59.9,48.25 59.9,48.78 ; 59.9,48.78 52.9,48.78 51.4,50.28 v1(44.5,50.28) v1(44,50.28) ; 59.9,48.78 59.9,49.52 60.53,50.16 J16.2
TL_VDD2V_O: length 7.6
  TOP w0.5: L2.2 C14.1 43.8,55.28 v1(44.4,54.68) v1(44.4,53.88)
  BOTTOM w0.5: J16.16 60.5,32.38 v1(59.7,31.58) v1(59.7,31.08)
TL_VDD3: length 10.4
  TOP w0.2: 34.8,54.16 34.78,54.18 v1(34.7,54.18) ; 34.8,54.48 U14.24
  TOP w0.4: v1(35.6,49.38) 34.25,50.73 34.25,53.33 v1(34.7,53.78) ; v1(34.7,53.78) v1(34.7,54.18) 34.7,54.38 34.8,54.48 ; v1(34.7,53.78) 34.8,53.68 34.8,52.88 C41.1
  TOP w0.5: v1(63.85,37.48) v1(63.85,37.83)
  BOTTOM w0.4: J16.12 63.63,37.46 63.65,37.48 v1(63.85,37.48) ; v1(35.6,49.38) v1(36.1,49.38)
TL_XC1: length 13.2
  TOP w0.2: C1.2 29.07,68.72 Y1.3 29.02,67.55 27.9,66.43 27.9,64.98 28.8,64.08 31.9,64.08 34,61.98 U14.39
TL_XC2: length 10
  TOP w0.2: U14.40 33.6,61.78 31.71,63.67 28.01,63.67 C2.2 27.6,64.6 26.59,65.62 Y1.1
VCOM: length 8
  TOP w0.5: v1(76.4,42.68) R35.1 R34.2
  BOTTOM w0.5: J17.17 2.81,29.84 3.4,30.42 v1(3.4,30.78) v1(3.4,31.4) 3.4,32.02 3.04,32.38 J17.15
VDW: length 10.9
  TOP w0.5: R35.2 R36.1 73.6,40.78 v1(72.4,39.58)
  BOTTOM w0.5: J17.18 9.11,29.84 9.8,29.15 v1(9.8,28.58) 9.8,27.88 9.22,27.3 J17.20
VUP: length 3.3
  TOP w0.5: v1(75.6,45.2) R34.1 R33.2
  BOTTOM w0.5: J17.16 v1(5.8,32.38)
N20012529: length 4.8
  TOP w0.2: R1.1 R3.1 46.04,60.83 Y2.1 46.99,60.64 C7.2
N20012531: length 5.1
  TOP w0.2: C8.2 47.78,62.16 Y2.2 45.9,61.83 R3.2 R2.1
N20028206: length 3.4
  TOP w0.5: U10.1 R37.1 R33.1
N20031284: length 3.2
  TOP w0.2: C23.1 31.25,52.58 32,53.33 U14.17
N20031302: length 5.8
  TOP w0.2: U14.26 35.97,56.08 36.16,55.89
  TOP w0.4: 36.35,54.13 36.35,55.7 36.16,55.89
  TOP w0.5: 36.35,54.13 37.44,53.04 37.94,53.04 38.7,52.28 L3.1
N20031350: length 4.2
  TOP w0.2: 37.4,56.46 36.98,56.88 U14.28
  TOP w0.5: 37.4,56.46 37.4,56.41 38.08,55.73 L2.1
N20031395: length 2.9
  TOP w0.2: U14.30 37.23,57.68 37.44,57.89
  TOP w0.4: 37.44,57.89 37.73,58.18 C13.1
N20031510: length 3.6
  TOP w0.5: 34.8,64.68 L1.2 C6.2 J1.1
N20031514: length 3
  TOP w0.2: U14.37 C5.2
  TOP w0.5: C5.2 L1.1
N20050417: length 2.3
  TOP w0.2: J11.3 14.73,61.61 R15.1
N20050429: length 2.2
  TOP w0.2: R14.1 15.53,61.51 J11.2
N20105309: length 6.2
  TOP w0.2: U14.12 26.3,55.68 EF2.1
N200358921: length 1.4
  TOP w0.2: R7.2 D4.A
N200359000: length 1.4
  TOP w0.2: R4.2 D1.A
N200359081: length 1.4
  TOP w0.2: R5.2 D2.A
N200359160: length 1.4
  TOP w0.2: R6.2 D3.A

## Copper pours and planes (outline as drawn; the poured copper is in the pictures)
GND on TOP: 1,0.3 0.51,0.51 0.3,1 0.3,67.43 1.1,69.38 3.05,70.18 74.55,70.18 76.5,69.38 77.3,67.43 77.3,4.19 75.95,2.84 55.26,2.84 52.72,0.3 ; 40 cut-outs
GND on BOTTOM: 1,0.3 0.51,0.51 0.3,1 0.3,67.43 1.1,69.38 3.05,70.18 74.55,70.18 76.5,69.38 77.3,67.43 77.3,4.19 75.95,2.84 55.26,2.84 52.72,0.3 ; 15 cut-outs
GND on GND: 1,0.3 0.51,0.51 0.3,1 0.3,67.43 1.1,69.38 3.05,70.18 74.55,70.18 76.5,69.38 77.3,67.43 77.3,4.19 75.95,2.84 55.26,2.84 52.72,0.3
VBAT_ADJ on POWER: 15.5,17.88 12.6,20.78 12.6,34.68 11.8,35.48 0.6,35.48 0.3,35.78 0.3,43.08 1.2,43.98 3.4,43.98 5,45.58 8,45.58 8.1,45.48 8.1,44.98 2.4,39.28 2.4,37.98 2.8,37.58 13.1,37.58 15.7,34.98 15.7,22.08 17.5,20.28 61.4,20.28 64.6,23.48 64.6,35.58 69.1,40.08 69.1,47.88 69.9,48.68 72.9,48.68 73.4,48.18 73.4,41.88 65.7,34.18 65.7,20.88 62.7,17.88
VBUS on POWER: 66.1,48.68 68.2,48.68 68.6,49.08 68.6,63.47 68.6,63.48 68.6,65.98 67.4,67.18 65,67.18 35.3,67.38 6.9,67.48 5.1,65.68 5.1,51.58 4.7,51.18 4.7,50.48 5.2,49.98 7.9,49.98 9.9,51.98 9.9,60.98 14.7,65.78 58.7,65.78 66.3,58.18 66.3,48.88
EXT_3V3 on POWER: 16.3,33.58 16.3,34.98 13.3,37.98 5.3,37.98 5.3,40.28 5.8,40.78 34.3,40.78 52.1,22.98 52.1,21.18 17.9,21.18 16.5,22.58 16.5,33.58
EXT_3V3 on POWER: 72.5,45.78 69.2,49.08 69.2,66.28 67.5,67.98 5.3,67.98 4.6,67.28 4.6,52.78 3.8,51.98 0.3,51.98 0.3,67.43 1.1,69.38 3.05,70.18 74.55,70.18 76.5,69.38 77.3,67.43 77.3,45.78
LEVEL_SHIFT on POWER: 2.3,37.38 2.3,39.98 7.9,45.58 12.6,45.58 12.8,45.38 12.8,41.08 9.9,38.18 9.9,37.48 9.8,37.38
TL_AVDD3 on POWER: 53.3,36.28 54.1,37.08 54.1,45.08 50.2,48.98 41.2,48.98 40.8,49.38 40.8,55.18 41.5,55.88 41.5,61.28 40.6,62.18 38.3,62.18 37.8,61.68 37.8,60.98 39.4,59.38 39.4,53.48 39.3,53.38 39.4,53.38 39.4,50.58 39.5,50.48 39.5,47.18 50.4,36.28
TL_FVDD2V on POWER: 58.3,32.48 58.3,31.68 58.1,31.48 56.9,31.48 55.1,33.28 55.1,46.28 51.8,49.58 41.9,49.58 41.2,50.28 41.2,55.18 41.9,55.88 41.9,58.18 43.9,58.18 44,58.08 44,55.98 42.9,54.88 42.9,53.18 43.7,52.38 51.6,52.38 57.1,46.88 57.1,33.68
TL_RFVDD1V2 on POWER: 31,62.68 55.5,62.68 62.7,55.48 62.7,49.38 63.1,48.98 65.3,48.98 65.6,49.28 65.6,57.98 62.9,60.58 58.3,65.38 31.2,65.38 30.6,64.78 30.6,64.68 30.4,64.48 30.4,63.28
TL_VBAT on POWER: 0.6,44.38 0.3,44.68 0.3,47.48 0.6,47.78 10.7,47.78 18.7,55.78 38.4,55.78 38.6,55.58 38.6,52.58 38.9,52.28 38.9,50.58 38.8,50.48 33.9,50.48 29.4,45.98 4.9,45.98 3.3,44.38
TL_VBUS on POWER: 0.8,48.18 0.3,48.68 0.3,49.88 0.6,50.18 4.3,50.18 4.9,49.58 9,49.58 10.8,51.38 10.8,60.88 14.6,64.68 29.5,64.68 30,64.18 30,62.48 30.2,62.28 36.7,62.28 37.1,61.88 37.1,60.08 38.05,59.13 38.05,57.63 38.06,57.64 38.06,57.14 37.1,56.18 18.5,56.18 10.5,48.18
TL_VDD2V_O on POWER: 59.7,30.28 60,30.58 60,33.28 60.2,33.48 60.2,54.08 57.1,57.18 44.8,57.18 44.4,56.78 44.4,55.98 43.3,54.88 43.3,53.28 43.8,52.78 51.8,52.78 57.6,46.98 57.6,33.78 58.7,32.68 58.7,30.58 59,30.28
TL_VDD3 on POWER: 61.6,38.68 63.7,38.68 64.5,37.88 64.5,36.08 63.7,35.28 63.7,24.78 60.3,21.38 55,21.38 36.3,40.08 36.3,40.18 31.1,45.38 31.1,47.08 33.9,49.88 37.8,49.88 38.6,49.08 38.6,43.78 55.2,27.18 57.4,27.18 60.8,30.58 60.8,37.88
VCOM on POWER: 1,0.3 0.51,0.51 0.3,1 0.3,31.48 0.8,31.98 3.5,31.98 4.3,31.18 4.3,13.08 8.3,9.08 70.7,9.08 74.1,12.48 74.1,35.08 75.8,36.78 75.8,42.98 76.1,43.28 77,43.28 77.3,42.98 77.3,4.19 75.95,2.84 55.26,2.84 52.72,0.3
VDW on POWER: 72.7,40.28 72.4,40.28 66.1,33.98 66.1,20.48 63.1,17.48 15.4,17.48 12.2,20.68 12.2,34.58 11.6,35.18 9.1,35.18 8.4,34.48 8.4,17.68 12.2,13.88 66.1,13.88 70.3,18.08 70.3,35.28 73.4,38.38 73.4,39.58
VUP on POWER: 9,9.48 4.8,13.68 4.8,31.38 3.8,32.38 0.7,32.38 0.3,32.78 0.3,34.88 0.5,35.08 7.2,35.08 7.9,34.38 7.9,17.28 11.9,13.28 66.3,13.28 71,17.98 71,35.38 73.9,38.28 73.9,48.18 74.3,48.58 77,48.58 77.3,48.28 77.3,45.98 77.3,43.88 77.1,43.68 76,43.68 75.4,43.08 75.4,37.08 73.7,35.38 73.7,12.68 70.5,9.48

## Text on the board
Ref Des/Silkscreen Bottom: GND | TDO | BEVK | EXT3V3 | SWS | TDI | NC | TCK | TMS | VBUS | VCOM | VBAT | SHIFT | VDW | USBVBUS | VADJ | EXT_3V3 | VUP | AVDD3 | FVDD2V | RFVDD1V2 | DVDD1V2 | VDDO3 | VDD2V_O | 1V2_O
User.Comments: RESET | IOREF | 3V3 | 5V | TX | RX | # | SCL | AREF | GND | 13 | 12 | 11 | 10 | 9 | 8 | 7 | 6 | 5 | 4 | 3 | 2 | 1 | 0 | SDA | A0 | A5 | VIN | A2 | A1 | A4 | A3 | [#=PWM] | www.arduino.cc | UNO_Rev3.01 | #4 | #5 | #3 | #1 | #2 | POWER | ANALOG IN | L | ON | DIGITAL | R10 | R9 | ESD1 | D1 | X1 | E1 | E2 | C3 | C4 | C5 | Cp1 | U2 | ZU4 | C12 | C2 | U1 | R2 | R1 | R3 | R8 | U5' | U5 | C8 | C10 | D2 | F1 | C1 | T1 | R6 | U3 | R14 | R15 | ICSP | R13 | Y2 | R12 | R7 | C11 | C9 | R4 | RESET-EN | R11 | C6 | L1 | X2 | C7 | Y1 | IOL | IOH | GROUND | Xduino
Ref Des/Silkscreen Top: PA0 | PA1 | PA2 | PA3 | PA4 | PA5 | PA6 | PA7 | PB0 | PB1 | PB2 | NC | PC0 | PC1 | PC2 | PC3 | PC4 | PC5 | TLSR9228H | C1T298A20_V1.0 | 2023-02-13 | PC6 | PC7 | PD0 | PD1 | PE0 | PE1 | PE2 | PE3 | PE4 | PE5 | PD2 | PE6 | PE7 | KEY4 | LEDW | LEDR | LEDB | LEDG | KEY1 | KEY2 | KEY3 | GND | CHIP_RESET
COMPVAL_TYPE_BOTTOM: FIGURE | SIZE | 0.3 | 0.5 | 0.9 | DRILL CHART: TOP to BOTTOM | ALL UNITS ARE IN MILLIMETERS | PLATED | NON-PLATED | QTY | 450 | 2 | 12
